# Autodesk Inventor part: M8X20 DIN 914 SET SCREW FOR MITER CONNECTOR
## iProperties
Created: 2006-02
Part Number: M8X20 DIN 914 SET SCREW FOR MITER CONNECTOR
Material: Steel, Mild
Description: Hexagon Socket Set Screw
Document SubType Name: Modeling
Standard: DIN 914
Designer: Andy Moles
Standards Organization: DIN
Language: en-US
Size Designation: M8 x 12
Categories: <MemberInstance><Categories><Category DisplayName="Fasteners" InternalName="e4da775c-781d-43d5-af7c-5136215cf5a6" Mnemonic="FSTN"><Category DisplayName="Bolts"
Density: 7.86 g/cm^3
Author: Andy Moles
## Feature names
1. Body [Revolution]
2. Slot [Extrusion]
3. Chamfer1
4. Chamfer2
